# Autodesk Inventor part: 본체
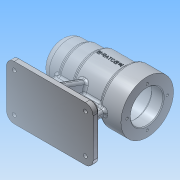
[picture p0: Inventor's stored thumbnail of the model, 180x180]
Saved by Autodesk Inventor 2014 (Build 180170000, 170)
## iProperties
Created: 2016-06
Part Number: 본체
Material: 알루미늄 6061
Document SubType Name: Modeling
Designer: net
Density: 2.71 g/cm^3
Appearance: 알루미늄 - 평지
Author: net
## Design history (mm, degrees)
sketch "스케치2"
  geometry: L1 (46, 35)-(-46, 35); L2 (-56, 25)-(-56, -25); L3 (-46, -35)-(46, -35); L4 (56, -25)-(56, 25); A1 r 10 centre (46, -25) between (46, -35) and (56, -25); A2 r 10 centre (46, 25) between (56, 25) and (46, 35); A3 r 10 centre (-46, 25) between (-46, 35) and (-56, 25); A4 r 10 centre (-46, -25) between (-56, -25) and (-46, -35); 1 further point
  constraints: 8 end point, 8 point on circle, 8 tangent, 4 centre point, 3 equal radius, 2 parallel, 1 horizontal, 1 perpendicular
  dimensions: "d5" = 10 radius of A1
extrude "돌출1" new body sketch "스케치2" distance "d6" = 10; taper "d7" = 0 deg
sketch "스케치3"
  geometry: A1 r 10 centre (-46, 25) between (-46, 35) and (-56, 25) reference; A2 r 10 centre (-46, -25) between (-56, -25) and (-46, -35) reference; A3 r 10 centre (46, -25) between (46, -35) and (56, -25) reference; A4 r 10 centre (46, 25) between (56, 25) and (46, 35) reference; 5 further points
  constraints: 4 coincident
hole "구멍1" sketch "스케치3" at (46, -25), (46, 25), (-46, 25), (-46, -25) diameter "d8" = 5; stored, may be unused: countersink angle "d12" = 90 deg, drill point angle "d14" = 118 deg; dims "d9" = 6, "d10" = 9, "d11" = 4, "d13" = 8
sketch "스케치4"
  geometry: L1 (-56, -25)-(-56, 25) reference; L2 (-46, 35)-(46, 35) reference; L3 (56, 25)-(56, -25) reference; L4 (46, -35)-(-46, -35) reference; L5 (36, 4)-(36, -4); L6 (-36, -4)-(-36, 4); L7 (-4, 28)-(4, 28); L8 (4, -28)-(-4, -28); L9 (4, -28)-(4, -4); L10 (4, 4)-(4, 28); L11 (-4, -28)-(-4, -4); L12 (-4, 4)-(-4, 28); L13 (-36, -4)-(-4, -4); L14 (4, -4)-(36, -4); L15 (-36, 4)-(-4, 4); L16 (4, 4)-(36, 4); C1 r 2.5 at (46, -25) reference; C2 r 2.5 at (-46, 25) reference; C3 r 2.5 at (-46, -25) reference; C4 r 2.5 at (46, 25) reference; A1 r 10 centre (-46, -25) between (-56, -25) and (-46, -35) reference; A2 r 10 centre (-46, 25) between (-46, 35) and (-56, 25) reference; A3 r 10 centre (46, 25) between (56, 25) and (46, 35) reference; A4 r 10 centre (46, -25) between (46, -35) and (56, -25) reference; 1 further point
  constraints: 24 end point
  dimensions: "d15" = 20 distance between parallel lines of L3 L5; "d16" = 20 distance between parallel lines of L6 L1; "d17" = 7 distance between parallel lines of L2 L7; "d18" = 7 distance between parallel lines of L4 L8
extrude "돌출2" join sketch "스케치4" distance "d23" = 70; taper "d24" = 0 deg
sketch "스케치5"
  geometry: L1 (0, 0)-(0, 10) reference; L2 (0, 10)-(50, 10) reference; L3 (50, 0)-(50, 10) reference; L4 (50, 0)-(0, 0) reference; L5 (21, 70)-(29, 70) reference; C1 r 25 at (25, 70); 1 further point
  constraints: 1 centre point, 1 midpoint
  dimensions: "d27" = 50 diameter of C1
extrude "돌출3" join sketch "스케치5" distance "d28" = 112; taper "d29" = 0 deg
node "작업 평면1"
sketch "스케치6"
  geometry: C1 r 27 at (0, 0); 1 further point
  constraints: 1 centre point
  dimensions: "d31" = 54 diameter of C1
extrude "돌출4" join sketch "스케치6" distance "d32" = 20; taper "d33" = 0 deg
sketch "스케치7"
  geometry: C1 r 30 at (0, 0); A1 r 25 centre (0, 0) between (4, -24.678) and (-4, -24.678) reference; 1 further point
  constraints: 1 centre point, 1 coincident
  dimensions: "d34" = 60 diameter of C1
extrude "돌출5" join sketch "스케치7" distance "d35" = 39; taper "d36" = 0 deg
sketch "스케치8"
  geometry: C1 r 34 at (0, 0); A1 r 30 centre (0, 0) between (4, -29.732) and (-4, -29.732) reference; 1 further point
  constraints: 1 centre point, 1 coincident
  dimensions: "d37" = 68 diameter of C1
extrude "돌출6" join sketch "스케치8" distance "d38" = 28; taper "d39" = 0 deg
feature "면 기울기1" dims angle "d40" = 20 deg
sketch "스케치9"
  geometry: C1 r 34 at (0, 0) reference; C2 r 21 at (0, 0); 1 further point
  constraints: 1 centre point, 1 coincident
  dimensions: "d41" = 42 diameter of C2
extrude "돌출7" cut sketch "스케치9" distance "d42" = 15; taper "d43" = 0 deg
sketch "스케치10"
  geometry: C1 r 21 at (0, 0) reference; C2 r 24 at (0, 0); 1 further point
  constraints: 1 centre point, 1 coincident
  dimensions: "d44" = 48 diameter of C2
extrude "돌출8" cut sketch "스케치10" distance "d45" = 54; taper "d46" = 0 deg
sketch "스케치11"
  geometry: C1 r 24 at (0, 0) reference; C2 r 21 at (0, 0); 1 further point
  constraints: 1 centre point, 1 coincident
  dimensions: "d47" = 42 diameter of C2
extrude "돌출9" cut sketch "스케치11" distance "d48" = 12; taper "d49" = 0 deg
sketch "스케치12"
  geometry: C1 r 21 at (0, 0) reference; C2 r 17.5 at (0, 0); 1 further point
  constraints: 1 centre point, 1 coincident
  dimensions: "d50" = 35 diameter of C2
extrude "돌출10" cut sketch "스케치12" distance "d51" = 18; taper "d52" = 0 deg
chamfer "모따기1" distance "d53" = 4; stored, may be unused: second distance "d54" = 2, angle "d55" = 45 deg
chamfer "모따기2" distance "d56" = 1; stored, may be unused: second distance "d57" = 2, angle "d58" = 45 deg
fillet "모깎기1" dims "d59" = 10
fillet "모깎기3" dims "d64" = 3
fillet "모깎기4" dims "d65" = 3
fillet "모깎기5" dims "d66" = 3
fillet "모깎기6" dims "d67" = 3
fillet "모깎기7" dims "d68" = 3
fillet "모깎기8" dims "d69" = 3
node "작업 평면2"
sketch "스케치14"
  geometry: L1 (56, 36)-(56, 104) reference; L2 (56, 36)-(56, 70); 2 further points
  constraints: 2 end point, 1 midpoint, 1 other
  dimensions: "d71" = 48 distance from line of point (8, 70) L1; "d72" = 0 vertical distance of point (8, 70) L2.end
feature "엠보싱1" sketch "스케치14" dims "d12" = 90 deg, "d73" = 0.5, "d74" = 0
sketch "스케치15"
  geometry: C1 r 34 at (0, 0) reference; C2 r 22 at (0, 0) reference; 6 further points
  constraints: 1 coincident, 6 other
  dimensions: "d75" = 26 distance of point (26, 0) C1.centre; "d78" = 360 deg dimension on point (0, 0) point (26, 0) (derived)
hole "구멍2" sketch "스케치15" at (0, 26), (26, 0), (0, -26), (-26, 0) diameter "d80" = 3.242; stored, may be unused: countersink angle "d84" = 90 deg, drill point angle "d86" = 118 deg; dims "d81" = 8, "d82" = 4, "d83" = 2, "d85" = 11
sketch "스케치16"
  geometry: C1 r 17.5 at (0, 0) reference; C2 r 16 at (0, 0); 1 further point
  constraints: 1 centre point, 1 coincident
  dimensions: "d87" = 32 diameter of C2
extrude "돌출12" cut sketch "스케치16" distance "d88" = 4; taper "d89" = 0 deg
sketch "스케치17"
  geometry: C1 r 16 at (0, 0) reference; C2 r 10.5 at (0, 0); 1 further point
  constraints: 1 centre point, 1 coincident
  dimensions: "d90" = 21 diameter of C2
extrude "돌출13" cut sketch "스케치17" distance "d91" = 3; taper "d92" = 0 deg
fillet "모깎기9" dims "d93" = 3
fillet "모깎기10" dims "d94" = 0.3
node "솔리드1"
node "절단 모서리 투영1"
node "절단 모서리 투영2"
other parameters: "d30" = -25
